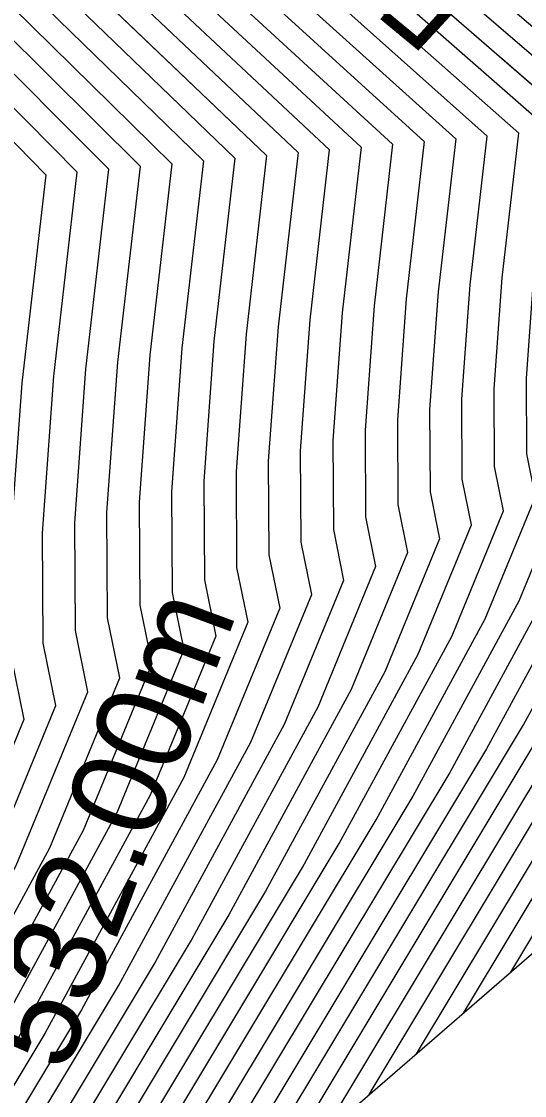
# Model space of a CAD drawing. Extents: x -866683 to -866410, y -1041951 to -1040252.
# Drawn here: x -866435.173 to -866433.576, y -1041930.632 to -1041927.226 of the extents above; entities that cross this region are included whole.
import ezdxf

# ---------------------------------------------------------------- set-up
doc = ezdxf.new("R2010")
doc.units = 0
for name, color, linetype in [('EXTERIOR', 7, 'Continuous'), ('V-HL', 7, 'Continuous'), ('V-VEDL', 7, 'Continuous'), ('V_po_cm', 7, 'Continuous')]:
    doc.layers.add(name, color=color, linetype=linetype)

msp = doc.modelspace()

# ---------------------------------------------------------------- linework, layer by layer
at = {"layer": 'EXTERIOR'}
msp.add_lwpolyline([(-866470.107, -1041899.606), (-866467.474, -1041915.319), (-866464.952, -1041936.638), (-866464.966, -1041937.083), (-866464.745, -1041941.128), (-866464.731, -1041942.196), (-866464.769, -1041945.786), (-866461.426, -1041946.157), (-866460.329, -1041945.918), (-866459.426, -1041945.724), (-866458.763, -1041945.697), (-866451.679, -1041950.508), (-866451.576, -1041945.087), (-866450.598, -1041944.936), (-866430.202, -1041927.282), (-866428.169, -1041926.387), (-866426.565, -1041925.108), (-866423.347, -1041921.351), (-866422.644, -1041920.368), (-866422.16, -1041919.445), (-866422.107, -1041897.411)], dxfattribs=at)
at = {"layer": 'V-HL'}
msp.add_lwpolyline([(-866435.0336, -1041927.0417), (-866434.3953, -1041927.6504), (-866434.4602, -1041928.2169), (-866434.4918, -1041928.6525), (-866434.49, -1041928.9571), (-866434.4548, -1041929.1309), (-866434.6579, -1041929.6236), (-866435.0992, -1041930.4354), (-866436.4582, -1041932.6971)], dxfattribs=at)
at = {"layer": 'V-VEDL'}
msp.add_lwpolyline([(-866450.1147, -1041916.1968), (-866448.8707, -1041917.8472), (-866447.9631, -1041918.5971), (-866447.3917, -1041918.4467), (-866445.5135, -1041919.3281), (-866442.3286, -1041921.2412), (-866437.8368, -1041924.1862), (-866434.8588, -1041926.2933), (-866433.3945, -1041927.5625), (-866433.444, -1041927.9938), (-866433.468, -1041928.3254), (-866433.4666, -1041928.5573), (-866433.4398, -1041928.6896), (-866433.5944, -1041929.0648), (-866433.9304, -1041929.6828), (-866434.965, -1041931.4047)], dxfattribs=at)
at = {"layer": 'V_po_cm'}
for points in [[(-866453.9556, -1041910.9838), (-866450.5491, -1041916.4822), (-866449.2051, -1041918.2601), (-866448.2204, -1041919.0667), (-866447.5949, -1041918.902), (-866445.7626, -1041919.7202), (-866442.7235, -1041921.5211), (-866438.4776, -1041924.3049), (-866435.6682, -1041926.3451), (-866434.2952, -1041927.6416), (-866434.3586, -1041928.1946), (-866434.3894, -1041928.6198), (-866434.3877, -1041928.9172), (-866434.3533, -1041929.0867), (-866434.5515, -1041929.5677), (-866434.9823, -1041930.3602), (-866436.3089, -1041932.5679)], [(-866453.7233, -1041911.5779), (-866450.5178, -1041916.7519), (-866449.2368, -1041918.4207), (-866448.2776, -1041919.1711), (-866447.64, -1041919.0032), (-866445.8179, -1041919.8073), (-866442.8113, -1041921.5833), (-866438.6201, -1041924.3313), (-866435.8481, -1041926.3566), (-866434.4954, -1041927.6592), (-866434.5619, -1041928.2392), (-866434.5942, -1041928.6852), (-866434.5924, -1041928.9971), (-866434.5563, -1041929.175), (-866434.7642, -1041929.6795), (-866435.216, -1041930.5107), (-866436.6075, -1041932.8263)], [(-866453.6072, -1041911.875), (-866450.5022, -1041916.8868), (-866449.2527, -1041918.5009), (-866448.3062, -1041919.2233), (-866447.6626, -1041919.0538), (-866445.8456, -1041919.8509), (-866442.8552, -1041921.6144), (-866438.6913, -1041924.3444), (-866435.938, -1041926.3623), (-866434.5954, -1041927.668), (-866434.6635, -1041928.2615), (-866434.6966, -1041928.7179), (-866434.6947, -1041929.0371), (-866434.6578, -1041929.2191), (-866434.8706, -1041929.7354), (-866435.3329, -1041930.586), (-866436.7568, -1041932.9556)], [(-866453.4911, -1041912.172), (-866450.4866, -1041917.0217), (-866449.2685, -1041918.5812), (-866448.3348, -1041919.2755), (-866447.6852, -1041919.1044), (-866445.8733, -1041919.8945), (-866442.899, -1041921.6455), (-866438.7625, -1041924.3576), (-866436.028, -1041926.3681), (-866434.6955, -1041927.6768), (-866434.7651, -1041928.2839), (-866434.799, -1041928.7506), (-866434.797, -1041929.0771), (-866434.7593, -1041929.2632), (-866434.9769, -1041929.7913), (-866435.4498, -1041930.6612), (-866436.9061, -1041933.0848)], [(-866437.0554, -1041933.2141), (-866435.5667, -1041930.7365), (-866435.0833, -1041929.8472), (-866434.8608, -1041929.3074), (-866434.8994, -1041929.1171), (-866434.9014, -1041928.7833), (-866434.8668, -1041928.3062), (-866434.7956, -1041927.6856), (-866436.1179, -1041926.3738), (-866438.8337, -1041924.3708), (-866442.9429, -1041921.6766), (-866445.901, -1041919.938), (-866447.7078, -1041919.155), (-866448.3633, -1041919.3276), (-866449.2844, -1041918.6615), (-866450.4709, -1041917.1565), (-866453.3749, -1041912.4691)], [(-866437.2047, -1041933.3433), (-866435.6835, -1041930.8117), (-866435.1896, -1041929.9031), (-866434.9623, -1041929.3515), (-866435.0017, -1041929.157), (-866435.0037, -1041928.816), (-866434.9684, -1041928.3285), (-866434.8957, -1041927.6944), (-866436.2078, -1041926.3796), (-866438.9049, -1041924.384), (-866442.9868, -1041921.7077), (-866445.9286, -1041919.9816), (-866447.7303, -1041919.2056), (-866448.3919, -1041919.3798), (-866449.3002, -1041918.7417), (-866450.4553, -1041917.2914), (-866453.2588, -1041912.7662)], [(-866437.354, -1041933.4725), (-866435.8004, -1041930.887), (-866435.296, -1041929.959), (-866435.0638, -1041929.3956), (-866435.1041, -1041929.197), (-866435.1061, -1041928.8487), (-866435.07, -1041928.3508), (-866434.9958, -1041927.7032), (-866436.2978, -1041926.3853), (-866438.9761, -1041924.3972), (-866443.0307, -1041921.7388), (-866445.9563, -1041920.0252), (-866447.7529, -1041919.2562), (-866448.4205, -1041919.432), (-866449.3161, -1041918.822), (-866450.4397, -1041917.4262), (-866453.1427, -1041913.0632)], [(-866453.0266, -1041913.3603), (-866450.424, -1041917.5611), (-866449.332, -1041918.9023), (-866448.4491, -1041919.4842), (-866447.7755, -1041919.3068), (-866445.984, -1041920.0687), (-866443.0746, -1041921.7699), (-866439.0473, -1041924.4104), (-866436.3877, -1041926.3911), (-866435.0958, -1041927.712), (-866435.1717, -1041928.3731), (-866435.2085, -1041928.8815), (-866435.2064, -1041929.237), (-866435.1653, -1041929.4398), (-866435.4023, -1041930.0148), (-866435.9173, -1041930.9623), (-866437.5033, -1041933.6018)], [(-866449.6536, -1041915.9546), (-866448.5274, -1041917.4486), (-866447.7058, -1041918.1275), (-866447.1885, -1041917.9913), (-866445.2645, -1041918.9359), (-866441.9336, -1041920.9613), (-866437.1959, -1041924.0675), (-866434.0493, -1041926.2415), (-866432.4938, -1041927.4834), (-866432.5293, -1041927.793), (-866432.5466, -1041928.031), (-866432.5456, -1041928.1975), (-866432.5263, -1041928.2925), (-866432.6373, -1041928.5618), (-866432.8785, -1041929.0055), (-866433.6212, -1041930.2416)], [(-866449.7048, -1041915.9815), (-866448.5656, -1041917.4929), (-866447.7344, -1041918.1797), (-866447.2111, -1041918.0419), (-866445.2921, -1041918.9795), (-866441.9775, -1041920.9924), (-866437.2672, -1041924.0807), (-866434.1393, -1041926.2473), (-866432.5939, -1041927.4921), (-866432.6309, -1041927.8153), (-866432.6489, -1041928.0637), (-866432.6479, -1041928.2375), (-866432.6278, -1041928.3366), (-866432.7437, -1041928.6177), (-866432.9954, -1041929.0807), (-866433.7706, -1041930.3708)], [(-866449.756, -1041916.0084), (-866448.6037, -1041917.5372), (-866447.7629, -1041918.2318), (-866447.2337, -1041918.0925), (-866445.3198, -1041919.0231), (-866442.0214, -1041921.0235), (-866437.3384, -1041924.0939), (-866434.2292, -1041926.253), (-866432.6939, -1041927.5009), (-866432.7326, -1041927.8376), (-866432.7513, -1041928.0964), (-866432.7503, -1041928.2775), (-866432.7293, -1041928.3807), (-866432.85, -1041928.6736), (-866433.1122, -1041929.156), (-866433.9199, -1041930.5)], [(-866434.0692, -1041930.6293), (-866433.2291, -1041929.2313), (-866432.9564, -1041928.7295), (-866432.8308, -1041928.4249), (-866432.8526, -1041928.3175), (-866432.8537, -1041928.1292), (-866432.8342, -1041927.8599), (-866432.794, -1041927.5097), (-866434.3192, -1041926.2588), (-866437.4096, -1041924.1071), (-866442.0653, -1041921.0546), (-866445.3475, -1041919.0666), (-866447.2562, -1041918.1431), (-866447.7915, -1041918.284), (-866448.6419, -1041917.5814), (-866449.8073, -1041916.0353)], [(-866434.3678, -1041930.8878), (-866433.4629, -1041929.3818), (-866433.169, -1041928.8412), (-866433.0338, -1041928.5131), (-866433.0573, -1041928.3974), (-866433.0585, -1041928.1946), (-866433.0374, -1041927.9045), (-866432.9942, -1041927.5273), (-866434.499, -1041926.2703), (-866437.552, -1041924.1335), (-866442.153, -1041921.1168), (-866445.4028, -1041919.1538), (-866447.3014, -1041918.2443), (-866447.8487, -1041918.3884), (-866448.7182, -1041917.67), (-866449.9098, -1041916.0892)], [(-866434.2185, -1041930.7585), (-866433.346, -1041929.3065), (-866433.0627, -1041928.7853), (-866432.9323, -1041928.469), (-866432.9549, -1041928.3575), (-866432.9561, -1041928.1619), (-866432.9358, -1041927.8822), (-866432.8941, -1041927.5185), (-866434.4091, -1041926.2645), (-866437.4808, -1041924.1203), (-866442.1091, -1041921.0857), (-866445.3752, -1041919.1102), (-866447.2788, -1041918.1937), (-866447.8201, -1041918.3362), (-866448.68, -1041917.6257), (-866449.8585, -1041916.0622)], [(-866434.5171, -1041931.017), (-866433.5798, -1041929.457), (-866433.2754, -1041928.8971), (-866433.1353, -1041928.5572), (-866433.1596, -1041928.4374), (-866433.1609, -1041928.2273), (-866433.1391, -1041927.9268), (-866433.0943, -1041927.5361), (-866434.589, -1041926.276), (-866437.6232, -1041924.1467), (-866442.1969, -1041921.1479), (-866445.4305, -1041919.1973), (-866447.324, -1041918.2949), (-866447.8773, -1041918.4406), (-866448.7563, -1041917.7143), (-866449.961, -1041916.1161)], [(-866450.0122, -1041916.143), (-866448.7945, -1041917.7586), (-866447.9059, -1041918.4927), (-866447.3465, -1041918.3455), (-866445.4582, -1041919.2409), (-866442.2408, -1041921.179), (-866437.6944, -1041924.1598), (-866434.6789, -1041926.2818), (-866433.1943, -1041927.5449), (-866433.2407, -1041927.9492), (-866433.2632, -1041928.26), (-866433.262, -1041928.4774), (-866433.2368, -1041928.6014), (-866433.3817, -1041928.953), (-866433.6966, -1041929.5323), (-866434.6664, -1041931.1462)], [(-866450.0635, -1041916.1699), (-866448.8326, -1041917.8029), (-866447.9345, -1041918.5449), (-866447.3691, -1041918.3961), (-866445.4859, -1041919.2845), (-866442.2847, -1041921.2101), (-866437.7656, -1041924.173), (-866434.7688, -1041926.2875), (-866433.2944, -1041927.5537), (-866433.3423, -1041927.9715), (-866433.3656, -1041928.2927), (-866433.3643, -1041928.5174), (-866433.3383, -1041928.6455), (-866433.4881, -1041929.0089), (-866433.8135, -1041929.6076), (-866434.8157, -1041931.2755)], [(-866435.1144, -1041931.534), (-866434.0473, -1041929.7581), (-866433.7008, -1041929.1207), (-866433.5413, -1041928.7337), (-866433.569, -1041928.5973), (-866433.5704, -1041928.3581), (-866433.5456, -1041928.0161), (-866433.4946, -1041927.5713), (-866434.9487, -1041926.299), (-866437.908, -1041924.1994), (-866442.3724, -1041921.2723), (-866445.5412, -1041919.3716), (-866447.4143, -1041918.4973), (-866447.9917, -1041918.6493), (-866448.9089, -1041917.8914), (-866450.166, -1041916.2237)], [(-866435.2637, -1041931.6632), (-866434.1641, -1041929.8333), (-866433.8071, -1041929.1765), (-866433.6428, -1041928.7779), (-866433.6713, -1041928.6373), (-866433.6728, -1041928.3908), (-866433.6472, -1041928.0384), (-866433.5947, -1041927.5801), (-866435.0387, -1041926.3048), (-866437.9792, -1041924.2126), (-866442.4163, -1041921.3034), (-866445.5689, -1041919.4152), (-866447.4369, -1041918.5479), (-866448.0203, -1041918.7015), (-866448.947, -1041917.9357), (-866450.2172, -1041916.2506)], [(-866435.413, -1041931.7924), (-866434.281, -1041929.9086), (-866433.9135, -1041929.2324), (-866433.7443, -1041928.822), (-866433.7737, -1041928.6773), (-866433.7752, -1041928.4235), (-866433.7488, -1041928.0607), (-866433.6947, -1041927.5889), (-866435.1286, -1041926.3105), (-866438.0504, -1041924.2258), (-866442.4602, -1041921.3345), (-866445.5965, -1041919.4588), (-866447.4594, -1041918.5985), (-866448.0488, -1041918.7536), (-866448.9852, -1041917.98), (-866450.2684, -1041916.2776)], [(-866450.3197, -1041916.3045), (-866449.0233, -1041918.0243), (-866448.0774, -1041918.8058), (-866447.482, -1041918.6491), (-866445.6242, -1041919.5023), (-866442.5041, -1041921.3656), (-866438.1216, -1041924.239), (-866435.2185, -1041926.3163), (-866433.7948, -1041927.5977), (-866433.8505, -1041928.083), (-866433.8775, -1041928.4562), (-866433.876, -1041928.7173), (-866433.8458, -1041928.8661), (-866434.0198, -1041929.2883), (-866434.3979, -1041929.9839), (-866435.5623, -1041931.9217)], [(-866450.4221, -1041916.3583), (-866449.0996, -1041918.1129), (-866448.1346, -1041918.9102), (-866447.5272, -1041918.7503), (-866445.6796, -1041919.5895), (-866442.5919, -1041921.4278), (-866438.264, -1041924.2653), (-866435.3984, -1041926.3278), (-866433.995, -1041927.6152), (-866434.0537, -1041928.1277), (-866434.0823, -1041928.5217), (-866434.0807, -1041928.7972), (-866434.0488, -1041928.9544), (-866434.2325, -1041929.4001), (-866434.6316, -1041930.1344), (-866435.8609, -1041932.1801)], [(-866450.3709, -1041916.3314), (-866449.0615, -1041918.0686), (-866448.106, -1041918.858), (-866447.5046, -1041918.6997), (-866445.6519, -1041919.5459), (-866442.548, -1041921.3967), (-866438.1928, -1041924.2521), (-866435.3085, -1041926.3221), (-866433.8949, -1041927.6065), (-866433.9521, -1041928.1054), (-866433.9799, -1041928.4889), (-866433.9783, -1041928.7572), (-866433.9473, -1041928.9102), (-866434.1262, -1041929.3442), (-866434.5148, -1041930.0591), (-866435.7116, -1041932.0509)], [(-866449.1378, -1041918.1572), (-866448.1632, -1041918.9624), (-866447.5497, -1041918.8009), (-866445.7072, -1041919.633), (-866442.6357, -1041921.4589), (-866438.3352, -1041924.2785), (-866435.4883, -1041926.3336), (-866434.095, -1041927.624), (-866434.1554, -1041928.15), (-866434.1847, -1041928.5544), (-866434.183, -1041928.8372), (-866434.1503, -1041928.9985), (-866434.3388, -1041929.456), (-866434.7485, -1041930.2096), (-866436.0102, -1041932.3094)], [(-866436.1595, -1041932.4386), (-866434.8654, -1041930.2849), (-866434.4452, -1041929.5119), (-866434.2518, -1041929.0426), (-866434.2853, -1041928.8772), (-866434.2871, -1041928.5871), (-866434.257, -1041928.1723), (-866434.1951, -1041927.6328), (-866435.5783, -1041926.3393), (-866438.4064, -1041924.2917), (-866442.6796, -1041921.49), (-866445.7349, -1041919.6766), (-866447.5723, -1041918.8515), (-866448.1918, -1041919.0146), (-866449.1759, -1041918.2014)], [(-866436.7688, -1041925.6147), (-866435.7581, -1041926.3508), (-866434.3953, -1041927.6504), (-866434.4602, -1041928.2169), (-866434.4918, -1041928.6525), (-866434.4918, -1041928.6655)], [(-866433.6524, -1041927.339), (-866433.3945, -1041927.5625), (-866433.444, -1041927.9938), (-866433.468, -1041928.3254), (-866433.4666, -1041928.5573), (-866433.4398, -1041928.6896), (-866433.5944, -1041929.0648), (-866433.9304, -1041929.6828), (-866434.965, -1041931.4047)]]:
    msp.add_lwpolyline(points, dxfattribs=at)

# ---------------------------------------------------------------- texts
for s, rotation, p in [('531.90m', 140.4355, (-866433.6964, -1041927.108)), ('532.00m', 69.6659, (-866435.0313, -1041930.5664))]:
    msp.add_text(s, height=0.3, rotation=rotation, dxfattribs=at).set_placement(p)

doc.saveas('drawing.dxf')
